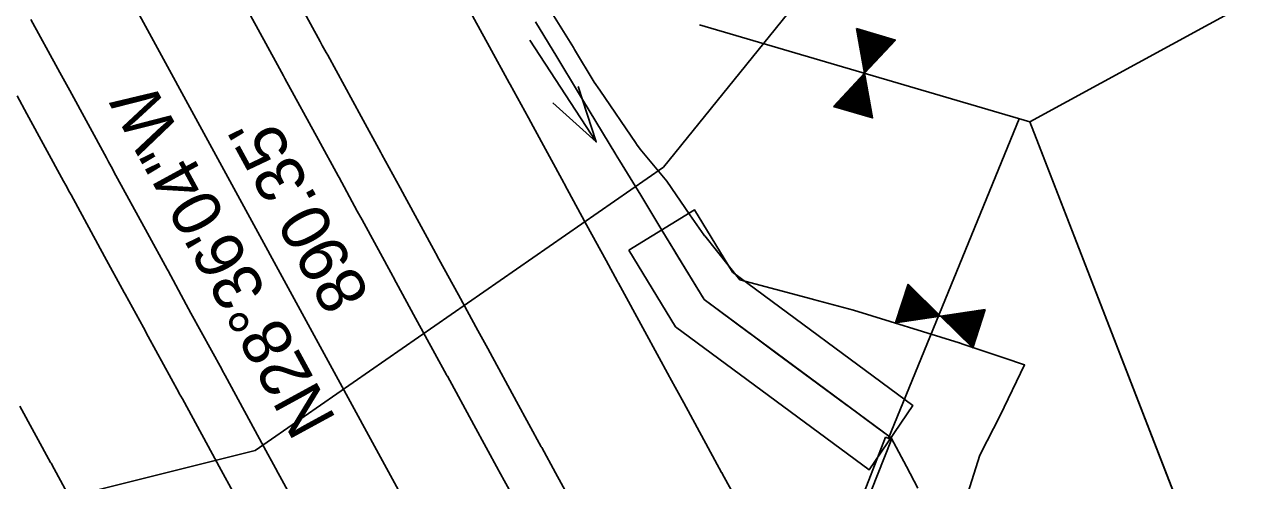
# Model space of a CAD drawing. Extents: x 1627557 to 1636561, y 783843 to 794002.
# Drawn here: x 1627975.8 to 1628128.2, y 784984.6 to 785040.7 of the extents above; entities that cross this region are included whole.
import ezdxf

# ---------------------------------------------------------------- set-up
doc = ezdxf.new("R2010")
doc.units = 0
for name, color, linetype in [('25 FT Buffer', 7, 'Continuous'), ('Ditch Lines', 7, 'Continuous'), ('Ditch with Dumped RipRap', 7, 'Continuous'), ('Flow Arrows', 7, 'Continuous'), ('GATE', 7, 'Continuous'), ('R_Clearzone', 7, 'Continuous'), ('R_Culvert', 7, 'Continuous'), ('R_Ditch', 7, 'Continuous'), ('R_Horz Alg', 7, 'Continuous'), ('R_Horz Alg Annot', 7, 'Continuous'), ('R_Proposed Const Limits', 7, 'Continuous'), ('R_Proposed Road', 7, 'Continuous'), ('R_Proposed Shoulder', 7, 'Continuous'), ('R_ROW', 7, 'Continuous'), ('R_ROW Annot', 7, 'Continuous'), ('Tangents', 7, 'Continuous')]:
    doc.layers.add(name, color=color, linetype=linetype)

msp = doc.modelspace()

# ---------------------------------------------------------------- linework, layer by layer
at = {"layer": '25 FT Buffer'}
for points in [[(1628355.58, 785125.53), (1628311.46, 785141.24), (1628266.6, 785150.06), (1628218.83, 785149.33), (1628170.24, 785124.54), (1628140.43, 785103.8), (1628095.21, 785070.36), (1628070.53, 785042.96), (1628054.55, 785023.15)], [(1628198.17, 784774.92), (1628099.65, 785028.73), (1628058.95, 785040.71)], [(1628054.55, 785023.15), (1628004.24, 784988.22), (1627960.38, 784977.27), (1627945.89, 784950.14), (1627929.03, 784949.04), (1627888.77, 784937.95), (1627849.63, 784928.54), (1627772.56, 784892.79), (1627744.38, 784877.73), (1627690.67, 784864.34), (1627668.83, 784866.74), (1627658.94, 784868.89)]]:
    msp.add_lwpolyline(points, dxfattribs=at)
at = {"layer": 'Ditch Lines'}
msp.add_lwpolyline([(1628082.56, 784989.8), (1628059.53, 785006.85), (1628054.32, 785015.4)], dxfattribs=at)
at = {"layer": 'Ditch with Dumped RipRap'}
msp.add_lwpolyline([(1628050.28, 785012.91), (1628056.02, 785003.49), (1628079.86, 784985.83), (1628085.26, 784993.76), (1628063.04, 785010.22), (1628058.36, 785017.89)], close=True, dxfattribs=at)
at = {"layer": 'Flow Arrows'}
msp.add_line((1628046.25, 785026.26), (1628038.06, 785038.82), dxfattribs=at)
msp.add_lwpolyline([(1628044.01, 785033.1), (1628046.25, 785026.26), (1628040.89, 785031.07)], dxfattribs=at)
at = {"layer": 'GATE'}
for p, q in [((1628078.32, 785040.2), (1628083.1, 785038.8)), ((1628078.34, 785040.09), (1628083.03, 785038.71)), ((1628078.36, 785039.98), (1628082.95, 785038.63)), ((1628078.38, 785039.87), (1628082.87, 785038.55)), ((1628078.4, 785039.76), (1628082.8, 785038.47)), ((1628078.42, 785039.65), (1628082.72, 785038.39)), ((1628078.44, 785039.54), (1628082.64, 785038.3)), ((1628078.46, 785039.43), (1628082.57, 785038.22)), ((1628078.48, 785039.32), (1628082.49, 785038.14)), ((1628078.5, 785039.21), (1628082.42, 785038.06)), ((1628078.52, 785039.1), (1628082.34, 785037.98)), ((1628078.54, 785038.99), (1628082.26, 785037.9)), ((1628078.55, 785038.88), (1628082.19, 785037.81)), ((1628078.57, 785038.77), (1628082.11, 785037.73)), ((1628078.59, 785038.66), (1628082.03, 785037.65)), ((1628078.61, 785038.55), (1628081.96, 785037.57)), ((1628078.63, 785038.44), (1628081.88, 785037.49)), ((1628078.65, 785038.33), (1628081.81, 785037.4)), ((1628078.67, 785038.22), (1628081.73, 785037.32)), ((1628078.69, 785038.11), (1628081.65, 785037.24)), ((1628078.71, 785038), (1628081.58, 785037.16)), ((1628078.73, 785037.89), (1628081.5, 785037.08)), ((1628078.75, 785037.78), (1628081.42, 785037)), ((1628078.77, 785037.67), (1628081.35, 785036.91)), ((1628078.79, 785037.56), (1628081.27, 785036.83)), ((1628078.81, 785037.45), (1628081.2, 785036.75)), ((1628078.83, 785037.34), (1628081.12, 785036.67)), ((1628078.85, 785037.23), (1628081.04, 785036.59)), ((1628078.87, 785037.12), (1628080.97, 785036.5)), ((1628078.89, 785037.01), (1628080.89, 785036.42)), ((1628078.91, 785036.9), (1628080.82, 785036.34)), ((1628078.93, 785036.79), (1628080.74, 785036.26)), ((1628078.95, 785036.68), (1628080.66, 785036.18)), ((1628078.97, 785036.57), (1628080.59, 785036.1)), ((1628078.99, 785036.46), (1628080.51, 785036.01)), ((1628079.01, 785036.35), (1628080.43, 785035.93)), ((1628079.03, 785036.24), (1628080.36, 785035.85)), ((1628079.05, 785036.13), (1628080.28, 785035.77)), ((1628079.07, 785036.02), (1628080.21, 785035.69)), ((1628079.09, 785035.91), (1628080.13, 785035.6)), ((1628079.11, 785035.8), (1628080.05, 785035.52)), ((1628079.13, 785035.69), (1628079.98, 785035.44)), ((1628079.15, 785035.58), (1628079.9, 785035.36)), ((1628079.17, 785035.47), (1628079.82, 785035.28)), ((1628079.19, 785035.36), (1628079.75, 785035.2)), ((1628079.21, 785035.25), (1628079.67, 785035.11)), ((1628079.23, 785035.14), (1628079.6, 785035.03)), ((1628079.25, 785035.03), (1628079.52, 785034.95)), ((1628079.27, 785034.92), (1628079.44, 785034.87)), ((1628078.06, 785033.38), (1628079.62, 785032.92)), ((1628078.14, 785033.47), (1628079.6, 785033.03)), ((1628078.21, 785033.55), (1628079.58, 785033.14)), ((1628078.29, 785033.63), (1628079.56, 785033.25)), ((1628078.37, 785033.71), (1628079.54, 785033.36)), ((1628078.44, 785033.79), (1628079.53, 785033.47)), ((1628078.52, 785033.87), (1628079.51, 785033.58)), ((1628078.59, 785033.96), (1628079.49, 785033.69)), ((1628078.67, 785034.04), (1628079.47, 785033.8)), ((1628078.75, 785034.12), (1628079.45, 785033.91)), ((1628078.82, 785034.2), (1628079.43, 785034.02)), ((1628078.9, 785034.28), (1628079.41, 785034.13)), ((1628078.98, 785034.37), (1628079.39, 785034.24)), ((1628079.05, 785034.45), (1628079.37, 785034.35)), ((1628079.13, 785034.53), (1628079.35, 785034.46)), ((1628079.2, 785034.61), (1628079.33, 785034.57)), ((1628079.28, 785034.69), (1628079.31, 785034.68)), ((1628079.29, 785034.81), (1628079.37, 785034.79)), ((1628076.61, 785031.83), (1628080, 785030.83)), ((1628076.69, 785031.91), (1628079.98, 785030.94)), ((1628076.77, 785031.99), (1628079.96, 785031.05)), ((1628076.84, 785032.07), (1628079.94, 785031.16)), ((1628076.92, 785032.16), (1628079.92, 785031.27)), ((1628076.99, 785032.24), (1628079.9, 785031.38)), ((1628077.07, 785032.32), (1628079.88, 785031.49)), ((1628077.15, 785032.4), (1628079.86, 785031.6)), ((1628077.22, 785032.48), (1628079.84, 785031.71)), ((1628077.3, 785032.57), (1628079.82, 785031.82)), ((1628077.38, 785032.65), (1628079.8, 785031.93)), ((1628077.45, 785032.73), (1628079.78, 785032.04)), ((1628077.53, 785032.81), (1628079.76, 785032.15)), ((1628077.6, 785032.89), (1628079.74, 785032.26)), ((1628077.68, 785032.97), (1628079.72, 785032.37)), ((1628077.76, 785033.06), (1628079.7, 785032.48)), ((1628077.83, 785033.14), (1628079.68, 785032.59)), ((1628077.91, 785033.22), (1628079.66, 785032.7)), ((1628077.99, 785033.3), (1628079.64, 785032.81)), ((1628075.55, 785030.68), (1628080.27, 785029.29)), ((1628075.62, 785030.77), (1628080.26, 785029.4)), ((1628075.7, 785030.85), (1628080.24, 785029.51)), ((1628075.78, 785030.93), (1628080.22, 785029.62)), ((1628075.85, 785031.01), (1628080.2, 785029.73)), ((1628075.93, 785031.09), (1628080.18, 785029.84)), ((1628076, 785031.17), (1628080.16, 785029.95)), ((1628076.08, 785031.26), (1628080.14, 785030.06)), ((1628076.16, 785031.34), (1628080.12, 785030.17)), ((1628076.23, 785031.42), (1628080.1, 785030.28)), ((1628076.31, 785031.5), (1628080.08, 785030.39)), ((1628076.39, 785031.58), (1628080.06, 785030.5)), ((1628076.46, 785031.67), (1628080.04, 785030.61)), ((1628076.54, 785031.75), (1628080.02, 785030.72)), ((1628098.34, 785029.11), (1628082.25, 784989.74)), ((1628084.73, 785008.66), (1628083.21, 785003.97)), ((1628084.81, 785008.58), (1628083.32, 785003.99)), ((1628084.89, 785008.5), (1628083.43, 785004.01)), ((1628084.97, 785008.42), (1628083.54, 785004.02)), ((1628085.05, 785008.35), (1628083.65, 785004.04)), ((1628085.13, 785008.27), (1628083.76, 785004.06)), ((1628085.21, 785008.19), (1628083.87, 785004.07)), ((1628085.29, 785008.11), (1628083.98, 785004.09)), ((1628085.37, 785008.03), (1628084.09, 785004.11)), ((1628085.45, 785007.95), (1628084.2, 785004.12)), ((1628085.53, 785007.87), (1628084.31, 785004.14)), ((1628085.61, 785007.8), (1628084.42, 785004.16)), ((1628085.69, 785007.72), (1628084.53, 785004.17)), ((1628085.77, 785007.64), (1628084.64, 785004.19)), ((1628085.85, 785007.56), (1628084.75, 785004.2)), ((1628085.93, 785007.48), (1628084.87, 785004.22)), ((1628086.01, 785007.4), (1628084.98, 785004.24)), ((1628086.08, 785007.33), (1628085.09, 785004.25)), ((1628086.16, 785007.25), (1628085.2, 785004.27)), ((1628086.24, 785007.17), (1628085.31, 785004.29)), ((1628086.32, 785007.09), (1628085.42, 785004.3)), ((1628086.4, 785007.01), (1628085.53, 785004.32)), ((1628086.48, 785006.93), (1628085.64, 785004.34)), ((1628086.56, 785006.85), (1628085.75, 785004.35)), ((1628086.64, 785006.78), (1628085.86, 785004.37)), ((1628086.72, 785006.7), (1628085.97, 785004.39)), ((1628086.8, 785006.62), (1628086.08, 785004.4)), ((1628086.88, 785006.54), (1628086.19, 785004.42)), ((1628086.96, 785006.46), (1628086.3, 785004.44)), ((1628087.04, 785006.38), (1628086.41, 785004.45)), ((1628087.12, 785006.31), (1628086.52, 785004.47)), ((1628087.2, 785006.23), (1628086.63, 785004.49)), ((1628087.28, 785006.15), (1628086.75, 785004.5)), ((1628087.36, 785006.07), (1628086.86, 785004.52)), ((1628087.44, 785005.99), (1628086.97, 785004.54)), ((1628087.52, 785005.91), (1628087.08, 785004.55)), ((1628087.6, 785005.83), (1628087.19, 785004.57)), ((1628087.68, 785005.76), (1628087.3, 785004.59)), ((1628087.76, 785005.68), (1628087.41, 785004.6)), ((1628087.84, 785005.6), (1628087.52, 785004.62)), ((1628087.92, 785005.52), (1628087.63, 785004.64)), ((1628088, 785005.44), (1628087.74, 785004.65)), ((1628088.08, 785005.36), (1628087.85, 785004.67)), ((1628088.16, 785005.29), (1628087.96, 785004.69)), ((1628088.24, 785005.21), (1628088.07, 785004.7)), ((1628088.31, 785005.13), (1628088.18, 785004.72)), ((1628088.39, 785005.05), (1628088.29, 785004.74)), ((1628088.47, 785004.97), (1628088.4, 785004.75)), ((1628088.55, 785004.89), (1628088.51, 785004.77)), ((1628088.63, 785004.81), (1628088.62, 785004.79)), ((1628088.75, 785004.81), (1628088.72, 785004.72)), ((1628088.86, 785004.82), (1628088.8, 785004.65)), ((1628088.97, 785004.84), (1628088.88, 785004.57)), ((1628089.08, 785004.86), (1628088.96, 785004.49)), ((1628089.19, 785004.87), (1628089.04, 785004.41)), ((1628089.3, 785004.89), (1628089.12, 785004.33)), ((1628089.41, 785004.91), (1628089.2, 785004.25)), ((1628089.53, 785004.92), (1628089.28, 785004.18)), ((1628089.64, 785004.94), (1628089.36, 785004.1)), ((1628089.75, 785004.96), (1628089.44, 785004.02)), ((1628089.86, 785004.97), (1628089.52, 785003.94)), ((1628089.97, 785004.99), (1628089.6, 785003.86)), ((1628090.08, 785005.01), (1628089.68, 785003.78)), ((1628090.19, 785005.02), (1628089.76, 785003.7)), ((1628090.3, 785005.04), (1628089.84, 785003.63)), ((1628090.41, 785005.06), (1628089.92, 785003.55)), ((1628090.52, 785005.07), (1628090, 785003.47)), ((1628090.63, 785005.09), (1628090.08, 785003.39)), ((1628090.74, 785005.11), (1628090.16, 785003.31)), ((1628090.85, 785005.12), (1628090.24, 785003.23)), ((1628090.96, 785005.14), (1628090.32, 785003.16)), ((1628091.07, 785005.16), (1628090.4, 785003.08)), ((1628091.18, 785005.17), (1628090.48, 785003)), ((1628091.29, 785005.19), (1628090.56, 785002.92)), ((1628091.4, 785005.21), (1628090.64, 785002.84)), ((1628091.52, 785005.22), (1628090.72, 785002.76)), ((1628091.63, 785005.24), (1628090.8, 785002.68)), ((1628091.74, 785005.26), (1628090.88, 785002.61)), ((1628091.85, 785005.27), (1628090.95, 785002.53)), ((1628091.96, 785005.29), (1628091.03, 785002.45)), ((1628092.07, 785005.31), (1628091.11, 785002.37)), ((1628092.18, 785005.32), (1628091.19, 785002.29)), ((1628092.29, 785005.34), (1628091.27, 785002.21)), ((1628092.4, 785005.36), (1628091.35, 785002.14)), ((1628092.51, 785005.37), (1628091.43, 785002.06)), ((1628092.62, 785005.39), (1628091.51, 785001.98)), ((1628092.73, 785005.41), (1628091.59, 785001.9)), ((1628092.84, 785005.42), (1628091.67, 785001.82)), ((1628092.95, 785005.44), (1628091.75, 785001.74)), ((1628093.06, 785005.46), (1628091.83, 785001.66)), ((1628093.17, 785005.47), (1628091.91, 785001.59)), ((1628093.28, 785005.49), (1628091.99, 785001.51)), ((1628093.39, 785005.51), (1628092.07, 785001.43)), ((1628093.51, 785005.52), (1628092.15, 785001.35)), ((1628093.62, 785005.54), (1628092.23, 785001.27)), ((1628093.73, 785005.56), (1628092.31, 785001.19)), ((1628093.84, 785005.57), (1628092.39, 785001.12)), ((1628093.95, 785005.59), (1628092.47, 785001.04)), ((1628094.06, 785005.61), (1628092.55, 785000.96)), ((1628094.17, 785005.62), (1628092.63, 785000.88))]:
    msp.add_line(p, q, dxfattribs=at)
for points in [[(1628078.32, 785040.22), (1628079.3, 785034.72), (1628083.11, 785038.81)], [(1628075.49, 785030.63), (1628079.3, 785034.72), (1628080.29, 785029.21)], [(1628084.67, 785008.72), (1628088.66, 785004.79), (1628083.13, 785003.96)], [(1628094.18, 785005.62), (1628088.66, 785004.79), (1628092.64, 785000.87)]]:
    msp.add_lwpolyline(points, close=True, dxfattribs=at)
at = {"layer": 'R_Clearzone'}
for points in [[(1628063.73, 784981.81), (1628061.82, 784985.32), (1628061.71, 784985.51), (1628061.69, 784985.54), (1628061.69, 784985.54), (1628057.03, 784994.1), (1628055.33, 784997.21), (1628055.33, 784997.21), (1628055.29, 784997.29), (1628052.24, 785002.88), (1628048.97, 785008.87), (1628048.96, 785008.9), (1628048.88, 785009.04), (1628047.45, 785011.66), (1628045.06, 785016.05), (1628042.67, 785020.44), (1628042.29, 785021.13), (1628042.24, 785021.21), (1628038.46, 785028.15), (1628037.88, 785029.22), (1628035.63, 785033.35), (1628035.51, 785033.56), (1628033.09, 785038), (1628028.96, 785045.57)], [(1627981.85, 784981.58), (1627979.45, 784985.97), (1627979.08, 784986.66), (1627979.03, 784986.75), (1627975.25, 784993.68)]]:
    msp.add_lwpolyline(points, dxfattribs=at)
at = {"layer": 'R_Culvert'}
for p, q in [((1628072.43, 784965.7), (1628081.9, 784989.88)), ((1628072.93, 784964.93), (1628082.6, 784989.6)), ((1628082.6, 784989.6), (1628081.9, 784989.88))]:
    msp.add_line(p, q, dxfattribs=at)
at = {"layer": 'R_Ditch'}
msp.add_lwpolyline([(1628085.88, 784983.6), (1628084.45, 784986.27), (1628082.56, 784989.8), (1628080.78, 784991.1), (1628077.23, 784993.72), (1628077.04, 784993.87), (1628077.01, 784993.89), (1628077.01, 784993.89), (1628068.37, 785000.28), (1628065.24, 785002.61), (1628065.24, 785002.61), (1628065.16, 785002.67), (1628059.53, 785006.85), (1628055.97, 785012.69), (1628055.95, 785012.72), (1628055.87, 785012.85), (1628054.32, 785015.4), (1628051.72, 785019.68), (1628049.13, 785023.96), (1628048.72, 785024.63), (1628048.67, 785024.72), (1628044.57, 785031.48), (1628043.94, 785032.52), (1628041.5, 785036.55), (1628041.37, 785036.75), (1628038.75, 785041.08)], dxfattribs=at)
at = {"layer": 'R_Horz Alg'}
msp.add_line((1628236.53, 784589.68), (1627810.31, 785371.39), dxfattribs=at)
at = {"layer": 'R_Proposed Const Limits'}
msp.add_lwpolyline([(1628090.49, 784978.17), (1628093.52, 784987.64), (1628093.54, 784987.7), (1628093.6, 784987.8), (1628096, 784992.56), (1628099.02, 784998.77), (1628096.44, 784999.64), (1628091.29, 785001.39), (1628091.01, 785001.49), (1628090.97, 785001.5), (1628090.97, 785001.5), (1628077.95, 785005.51), (1628073.03, 785006.86), (1628073.03, 785006.86), (1628072.9, 785006.89), (1628063.94, 785009.26), (1628059.61, 785014.67), (1628059.58, 785014.7), (1628059.49, 785014.83), (1628057.79, 785017.29), (1628054.93, 785021.43), (1628051.67, 785025.35), (1628051.22, 785025.99), (1628051.16, 785026.08), (1628046.69, 785032.64), (1628046, 785033.64), (1628043.56, 785037.67), (1628043.44, 785037.88), (1628040.79, 785042.19)], dxfattribs=at)
at = {"layer": 'R_Proposed Road'}
for points in [[(1628035.96, 784982.61), (1628034.26, 784985.72), (1628034.26, 784985.72), (1628034.22, 784985.8), (1628031.17, 784991.39), (1628027.9, 784997.38), (1628027.88, 784997.41), (1628027.81, 784997.55), (1628026.38, 785000.17), (1628023.99, 785004.56), (1628021.6, 785008.95), (1628021.22, 785009.64), (1628021.17, 785009.73), (1628017.39, 785016.66), (1628016.81, 785017.73), (1628014.56, 785021.86), (1628014.44, 785022.07), (1628012.02, 785026.51), (1628007.89, 785034.08), (1628007.71, 785034.42), (1628007.23, 785035.29), (1628006.97, 785035.77), (1628002.45, 785044.07)], [(1628010.1, 784979.9), (1628006.83, 784985.89), (1628006.81, 784985.92), (1628006.74, 784986.06), (1628005.31, 784988.68), (1628002.92, 784993.07), (1628000.52, 784997.46), (1628000.15, 784998.15), (1628000.1, 784998.24), (1627996.32, 785005.17), (1627995.74, 785006.24), (1627993.49, 785010.37), (1627993.37, 785010.58), (1627990.95, 785015.02), (1627986.82, 785022.59), (1627986.64, 785022.93), (1627986.16, 785023.8), (1627985.9, 785024.28), (1627981.38, 785032.58), (1627980.16, 785034.81), (1627979.91, 785035.27), (1627976.59, 785041.36)]]:
    msp.add_lwpolyline(points, dxfattribs=at)
at = {"layer": 'R_Proposed Shoulder'}
for points in [[(1628045.89, 784976.92), (1628041.23, 784985.48), (1628039.53, 784988.59), (1628039.53, 784988.59), (1628039.48, 784988.67), (1628036.44, 784994.26), (1628033.17, 785000.25), (1628033.15, 785000.29), (1628033.08, 785000.43), (1628031.65, 785003.04), (1628029.26, 785007.43), (1628026.86, 785011.82), (1628026.49, 785012.51), (1628026.44, 785012.6), (1628022.66, 785019.53), (1628022.08, 785020.6), (1628019.82, 785024.73), (1628019.71, 785024.94), (1628017.29, 785029.38), (1628013.16, 785036.95), (1628012.98, 785037.29), (1628012.5, 785038.16), (1628012.24, 785038.64), (1628007.72, 785046.94)], [(1628001.47, 784983.19), (1628000.04, 784985.81), (1627997.65, 784990.2), (1627995.26, 784994.59), (1627994.88, 784995.27), (1627994.83, 784995.36), (1627991.05, 785002.3), (1627990.47, 785003.37), (1627988.22, 785007.5), (1627988.1, 785007.71), (1627985.68, 785012.15), (1627981.55, 785019.72), (1627981.37, 785020.05), (1627980.9, 785020.93), (1627980.63, 785021.41), (1627976.11, 785029.71), (1627974.89, 785031.94)]]:
    msp.add_lwpolyline(points, dxfattribs=at)
at = {"layer": 'R_ROW'}
for p, q in [((1628099.65, 785028.73), (1628058.95, 785040.71)), ((1628198.17, 784774.92), (1628099.65, 785028.73))]:
    msp.add_line(p, q, dxfattribs=at)
at = {"layer": 'R_ROW Annot'}
msp.add_lwpolyline([(1628099.65, 785028.73), (1628165.5, 785064.63), (1628191.84, 785078.99)], dxfattribs=at)

# ---------------------------------------------------------------- texts
at = {"layer": 'R_Horz Alg Annot'}
msp.add_text('N28%%d36\'04"W', height=6, rotation=118.601, dxfattribs=at).set_placement((1628014.29, 784992.05))
at = {"layer": 'Tangents'}
msp.add_text("890.35'", height=6, rotation=118.601, dxfattribs=at).set_placement((1628018.45, 785007.4))

doc.saveas('drawing.dxf')
